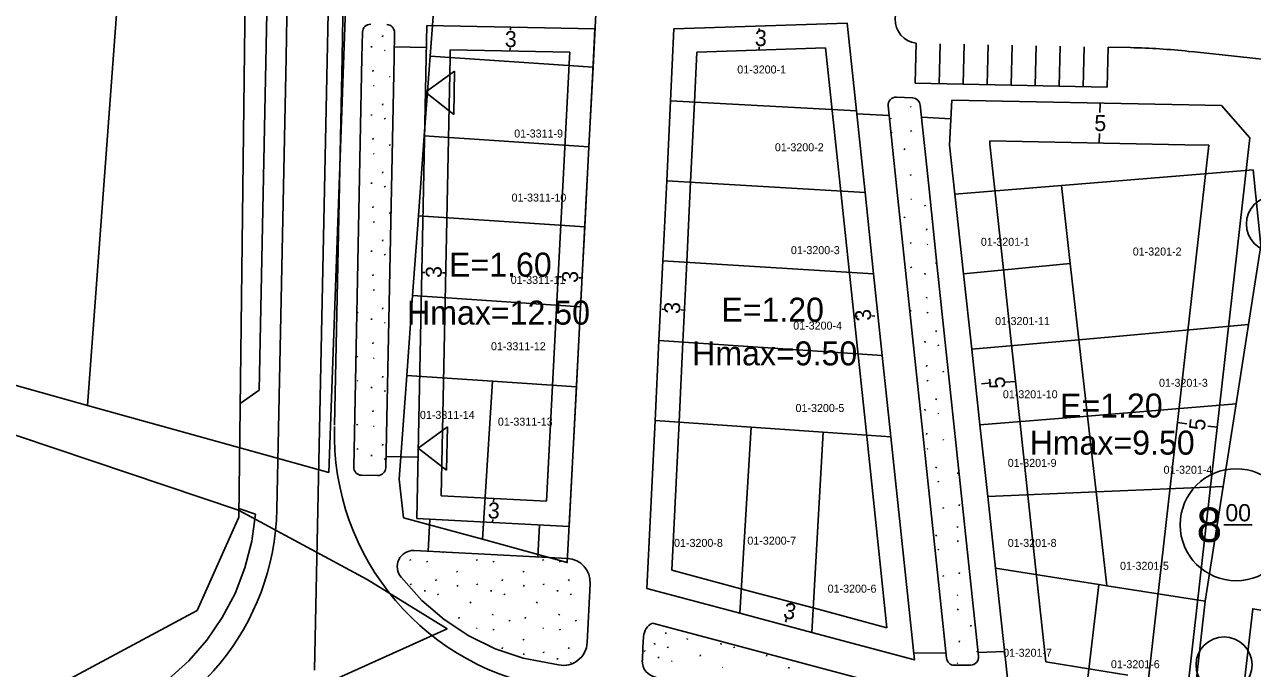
# Model space of a CAD drawing. Extents: x 419396 to 421519, y 4453567 to 4456767.
# Drawn here: x 420396.5 to 420549.9, y 4454436.5 to 4454516.9 of the extents above; entities that cross this region are included whole.
import ezdxf

# ---------------------------------------------------------------- set-up
doc = ezdxf.new("R2010")
doc.units = 0
for name, color, linetype in [('0_KADASTRO', 7, 'Continuous'), ('Level 16', 7, 'Continuous'), ('Level 20', 7, 'Continuous'), ('Level 28', 7, 'Continuous'), ('Level 29', 7, 'Continuous'), ('Level 30', 7, 'Continuous'), ('Level 41', 7, 'Continuous'), ('Level 55', 7, 'Continuous'), ('Level 58', 7, 'Continuous'), ('Level 62', 7, 'Continuous'), ('Level 9', 7, 'Continuous')]:
    doc.layers.add(name, color=color, linetype=linetype)

msp = doc.modelspace()

# ---------------------------------------------------------------- linework, layer by layer
at = {"layer": '0_KADASTRO'}
for points in [[(420388.29, 4454473.82), (420396.15, 4454590.13), (420397.27, 4454605.49), (420411.29, 4454607.72), (420413.06, 4454586.21), (420404.4, 4454469.34)], [(420404.4, 4454469.34), (420413.06, 4454586.21), (420428.47, 4454594.05), (420435.75, 4454599.28), (420439.04, 4454586.15), (420434.51, 4454460.97)], [(420447.18, 4454512.99), (420447.92, 4454522.96), (420468.06, 4454521.61), (420467.54, 4454511.62)], [(420477.22, 4454507.39), (420477.65, 4454516.39), (420499.29, 4454517.1), (420500.44, 4454506.16)], [(420446.46, 4454503.01), (420447.18, 4454512.99), (420467.54, 4454511.62), (420467.02, 4454501.64)], [(420476.74, 4454497.41), (420477.22, 4454507.39), (420500.44, 4454506.16), (420501.52, 4454495.96)], [(420445.72, 4454493.04), (420446.46, 4454503.01), (420467.02, 4454501.64), (420466.5, 4454491.64)], [(420320.37, 4454499), (420353.67, 4454483.99), (420381.85, 4454470.14), (420423.24, 4454456.24), (420439.33, 4454447.56), (420449.3, 4454441.41), (420436.11, 4454435.44), (420420.26, 4454427.93), (420390.68, 4454416.1), (420329.86, 4454402.38), (420323.67, 4454464.08)], [(420526.05, 4454496.81), (420550, 4454498.77), (420550.96, 4454489.32), (420549.42, 4454479.43), (420528.24, 4454477.55), (420527.16, 4454487.06)], [(420476.25, 4454487.42), (420476.74, 4454497.41), (420501.52, 4454495.96), (420502.59, 4454485.77)], [(420512.75, 4454495.73), (420526.05, 4454496.81), (420527.16, 4454487.06), (420513.83, 4454485.79)], [(420445, 4454483.07), (420445.72, 4454493.04), (420466.5, 4454491.64), (420465.98, 4454481.66)], [(420475.77, 4454477.43), (420476.25, 4454487.42), (420502.59, 4454485.77), (420503.67, 4454475.58)], [(420513.83, 4454485.79), (420527.16, 4454487.06), (420528.24, 4454477.55), (420514.85, 4454476.35)], [(420444.26, 4454473.08), (420445, 4454483.07), (420465.98, 4454481.66), (420465.46, 4454471.67), (420454.98, 4454472.37)], [(420528.24, 4454477.55), (420549.42, 4454479.43), (420547.87, 4454469.55), (420529.33, 4454468.01)], [(420475.29, 4454467.43), (420475.77, 4454477.43), (420503.67, 4454475.58), (420504.75, 4454465.39), (420496.28, 4454465.98), (420487.29, 4454466.6)], [(420514.85, 4454476.35), (420528.24, 4454477.55), (420529.33, 4454468.01), (420515.87, 4454466.9)], [(420443.31, 4454460.12), (420444.26, 4454473.08), (420454.98, 4454472.37), (420453.71, 4454452.6), (420443.86, 4454455.3)], [(420453.71, 4454452.6), (420454.98, 4454472.37), (420465.46, 4454471.67), (420464.32, 4454449.7)], [(420529.33, 4454468.01), (420547.87, 4454469.55), (420546.26, 4454459.18), (420530.4, 4454458.52)], [(420474.27, 4454446.46), (420475.29, 4454467.43), (420487.29, 4454466.6), (420485.86, 4454443.37)], [(420515.87, 4454466.9), (420529.33, 4454468.01), (420530.4, 4454458.52), (420516.85, 4454457.96)], [(420485.86, 4454443.37), (420487.29, 4454466.6), (420496.28, 4454465.98), (420494.89, 4454440.95)], [(420494.89, 4454440.95), (420496.28, 4454465.98), (420504.75, 4454465.39), (420507.69, 4454437.53)], [(420516.85, 4454457.96), (420530.4, 4454458.52), (420531.74, 4454446.8), (420530.73, 4454446.96), (420521.76, 4454448.38), (420517.81, 4454449.01)], [(420530.4, 4454458.52), (420546.26, 4454459.18), (420544.03, 4454444.85), (420531.74, 4454446.8)], [(420517.81, 4454449.01), (420521.76, 4454448.38), (420530.73, 4454446.96), (420528.91, 4454431.42), (420520.67, 4454432.78), (420519.55, 4454432.97)], [(420528.91, 4454431.42), (420530.73, 4454446.96), (420531.74, 4454446.8), (420544.03, 4454444.85), (420542.26, 4454429.23), (420533.58, 4454430.66)], [(420547.89, 4454425.95), (420548.01, 4454426.99), (420549.96, 4454443.91), (420562.54, 4454441.84), (420560.5, 4454423.87)]]:
    msp.add_lwpolyline(points, close=True, dxfattribs=at)
at = {"layer": 'Level 16'}
for p, q in [((420450.25, 4454511.11), (420446.59, 4454508.49)), ((420450.14, 4454505.71), (420450.25, 4454511.11)), ((420446.59, 4454508.49), (420450.14, 4454505.71)), ((420449.35, 4454466.64), (420445.7, 4454464.01)), ((420449.24, 4454461.24), (420449.35, 4454466.64)), ((420445.7, 4454464.01), (420449.24, 4454461.24))]:
    msp.add_line(p, q, dxfattribs=at)
at = {"layer": 'Level 20'}
for p, q in [((420457.22, 4454516.62), (420457.21, 4454516.22)), ((420488.31, 4454516.44), (420488.3, 4454516.04)), ((420449.7, 4454513.77), (420449.68, 4454512.81)), ((420449.7, 4454513.77), (420464.62, 4454513.47)), ((420457.16, 4454513.62), (420457.17, 4454514.02)), ((420464.59, 4454512.81), (420464.62, 4454513.47)), ((420480.52, 4454513.49), (420496.59, 4454514.01)), ((420488.3, 4454513.75), (420488.31, 4454514.15)), ((420449.68, 4454512.81), (420448.57, 4454458.03)), ((420461.71, 4454457.35), (420464.59, 4454512.81)), ((420530.89, 4454507.13), (420530.87, 4454505.93)), ((420517.1, 4454501.99), (420517.12, 4454502.41)), ((420541.46, 4454501.92), (420517.12, 4454502.41)), ((420530.79, 4454502.13), (420530.81, 4454503.33)), ((420544.46, 4454501.85), (420536.64, 4454432.5)), ((420541.46, 4454501.92), (420541.46, 4454501.92)), ((420544.46, 4454501.85), (420541.46, 4454501.92)), ((420446.14, 4454485.96), (420446.54, 4454485.95)), ((420449.14, 4454485.9), (420448.74, 4454485.91)), ((420463.17, 4454485.41), (420463.57, 4454485.39)), ((420466.16, 4454485.26), (420465.76, 4454485.28)), ((420476.16, 4454481.36), (420476.56, 4454481.33)), ((420478.9, 4454481.24), (420478.5, 4454481.26)), ((420500.16, 4454480.45), (420500.56, 4454480.45)), ((420502.75, 4454480.5), (420502.35, 4454480.51)), ((420516.07, 4454472.05), (420517.26, 4454472.15)), ((420520.29, 4454472.33), (420519.09, 4454472.25)), ((420540.55, 4454467.18), (420541.74, 4454467.04)), ((420545.52, 4454466.62), (420544.33, 4454466.75)), ((420448.57, 4454458.03), (420461.71, 4454457.35)), ((420455.14, 4454457.69), (420455.12, 4454457.29)), ((420454.99, 4454454.69), (420455.01, 4454455.09)), ((420492.25, 4454444.76), (420492.16, 4454444.37)), ((420491.59, 4454442.26), (420491.7, 4454442.64))]:
    msp.add_line(p, q, dxfattribs=at)
for points in [[(420477.38, 4454448.74), (420478.28, 4454467.29), (420478.77, 4454477.29), (420479.25, 4454487.27), (420479.73, 4454497.26), (420480.21, 4454507.25), (420480.52, 4454513.49)], [(420496.59, 4454514.01), (420497.46, 4454505.84), (420498.54, 4454495.65), (420499.61, 4454485.46), (420500.69, 4454475.26), (420501.77, 4454465.07), (420504.25, 4454441.55)], [(420524.11, 4454437.28), (420522.78, 4454449.54), (420521.82, 4454458.49), (420520.84, 4454467.44), (420519.82, 4454476.89), (420518.8, 4454486.33), (420517.1, 4454501.99)], [(420504.25, 4454441.55), (420495.67, 4454443.85), (420486.64, 4454446.26), (420477.38, 4454448.74)], [(420534.35, 4454435.6), (420529.72, 4454436.36), (420524.11, 4454437.28)]]:
    msp.add_lwpolyline(points, dxfattribs=at)
at = {"layer": 'Level 28'}
for p, q in [((420438.74, 4454516), (420438.67, 4454512.81)), ((420438.74, 4454516), (420438.67, 4454512.81)), ((420442.74, 4454515.92), (420442.68, 4454512.81)), ((420442.74, 4454515.92), (420442.68, 4454512.81)), ((420442.7, 4454514.16), (420446.7, 4454514.08)), ((420438.67, 4454512.81), (420437.64, 4454461.63)), ((420438.67, 4454512.81), (420437.64, 4454461.63)), ((420442.68, 4454512.81), (420441.64, 4454461.55)), ((420442.68, 4454512.81), (420441.64, 4454461.55)), ((420507.47, 4454507.76), (420505.44, 4454507.86)), ((420504.52, 4454505.57), (420500.48, 4454505.78)), ((420546.04, 4454506.82), (420549.6, 4454502.77)), ((420512.25, 4454505.17), (420508.57, 4454505.37)), ((420425.83, 4454471.25), (420423.46, 4454469.58)), ((420441.67, 4454462.96), (420445.67, 4454462.88)), ((420438.62, 4454460.61), (420440.62, 4454460.57)), ((420438.62, 4454460.61), (420440.62, 4454460.57)), ((420423.3, 4454456.43), (420425.36, 4454455.74)), ((420464.55, 4454454.19), (420445.51, 4454455.18)), ((420447.16, 4454455.09), (420446.95, 4454451.1)), ((420460.86, 4454454.38), (420460.66, 4454450.39)), ((420445.18, 4454451.19), (420464.34, 4454450.2)), ((420443.58, 4454447.86), (420446.17, 4454444.96)), ((420467.18, 4454447.05), (420466.8, 4454439.69)), ((420446.17, 4454444.96), (420448.95, 4454442.56)), ((420448.95, 4454442.56), (420452.02, 4454440.54)), ((420452.02, 4454440.54), (420455.32, 4454438.93)), ((420473.78, 4454439.09), (420473.85, 4454440.44)), ((420455.32, 4454438.93), (420458.8, 4454437.76)), ((420473.7, 4454437.46), (420473.78, 4454439.09)), ((420511.62, 4454438.4), (420507.6, 4454438.38)), ((420518.94, 4454438.57), (420515.64, 4454438.44)), ((420458.8, 4454437.76), (420463.23, 4454436.9)), ((420512.7, 4454436.85), (420514.71, 4454436.88))]:
    msp.add_line(p, q, dxfattribs=at)
for points in [[(420504.4, 4454506.76), (420505.5, 4454496.38), (420506.57, 4454486.19), (420507.65, 4454476), (420508.73, 4454465.81), (420511.69, 4454437.74)], [(420508.41, 4454506.86), (420509.48, 4454496.8), (420510.55, 4454486.61), (420511.63, 4454476.42), (420512.71, 4454466.23), (420515.69, 4454437.99)], [(420502.46, 4454434.79), (420493.86, 4454437.09), (420484.83, 4454439.5), (420474.97, 4454442.13)]]:
    msp.add_lwpolyline(points, dxfattribs=at)
for centre, radius, start, end in [((420439.74, 4454515.98), 1, 88.8411, 178.8411), ((420439.74, 4454515.98), 1, 88.8411, 178.8411), ((420441.74, 4454515.94), 1, 358.8411, 88.8411), ((420441.74, 4454515.94), 1, 358.8411, 88.8411), ((420505.39, 4454506.86), 1, 87.0144, 186.0491), ((420507.41, 4454506.76), 1, 6.0413, 87.0184), ((420438.64, 4454461.61), 1, 178.8411, 268.8411), ((420438.64, 4454461.61), 1, 178.8411, 268.8411), ((420440.64, 4454461.57), 1, 268.8411, 358.8411), ((420440.64, 4454461.57), 1, 268.8411, 358.8411), ((420445.07, 4454449.19), 2, 87.0363, 221.7532), ((420464.19, 4454447.2), 3, 357.0363, 87.0363), ((420475.85, 4454440.34), 2, 116.0278, 177.0363), ((420463.81, 4454439.84), 3, 258.9123, 357.0363), ((420514.69, 4454437.88), 1, 271.0633, 6.0242), ((420475.69, 4454437.36), 2, 177.0363, 262.6282), ((420512.69, 4454437.85), 1, 186.0244, 271.0368)]:
    msp.add_arc(centre, radius, start, end, dxfattribs=at)
at = {"layer": 'Level 29'}
for p, q in [((420427.92, 4454574.73), (420425.83, 4454471.25)), ((420446.68, 4454512.81), (420446.76, 4454516.83)), ((420446.76, 4454516.83), (420467.78, 4454516.41)), ((420467.78, 4454516.41), (420467.59, 4454512.81)), ((420477.65, 4454516.39), (420499.29, 4454517.1)), ((420445.51, 4454455.18), (420446.68, 4454512.81)), ((420467.59, 4454512.81), (420464.55, 4454454.2)), ((420512.08, 4454501.85), (420512.37, 4454507.5)), ((420512.37, 4454507.5), (420541.99, 4454506.91)), ((420541.99, 4454506.91), (420546.04, 4454506.82)), ((420549.6, 4454502.77), (420541.04, 4454426.89))]:
    msp.add_line(p, q, dxfattribs=at)
for points in [[(420474.27, 4454446.46), (420475.29, 4454467.43), (420475.77, 4454477.43), (420476.25, 4454487.42), (420476.74, 4454497.41), (420477.22, 4454507.39), (420477.65, 4454516.39)], [(420499.29, 4454517.1), (420500.44, 4454506.16), (420501.52, 4454495.96), (420502.59, 4454485.77), (420503.67, 4454475.58), (420504.75, 4454465.39), (420507.69, 4454437.53)], [(420519.55, 4454432.97), (420517.81, 4454449.01), (420516.85, 4454457.96), (420515.87, 4454466.9), (420514.85, 4454476.35), (420513.83, 4454485.79), (420512.08, 4454501.85)], [(420425.36, 4454455.74), (420424.89, 4454452.35), (420424.04, 4454449.04), (420422.81, 4454445.84), (420421.22, 4454442.82), (420419.28, 4454440), (420417.04, 4454437.42), (420414.51, 4454435.11), (420411.73, 4454433.12), (420408.74, 4454431.46), (420405.58, 4454430.16), (420402.29, 4454429.23)], [(420507.69, 4454437.53), (420494.89, 4454440.95), (420485.86, 4454443.37), (420474.27, 4454446.46)]]:
    msp.add_lwpolyline(points, dxfattribs=at)
at = {"layer": 'Level 41'}
for p, q in [((420441.22, 4454515.39), (420441.29, 4454515.55)), ((420439.85, 4454514.22), (420439.87, 4454514.06)), ((420441.48, 4454513.75), (420441.55, 4454513.64)), ((420440.02, 4454511.07), (420440.09, 4454511.23)), ((420442.11, 4454510.46), (420442.18, 4454510.35)), ((420440.13, 4454509.34), (420440.2, 4454509.23)), ((420441.22, 4454506.88), (420441.29, 4454507.04)), ((420439.85, 4454505.71), (420439.87, 4454505.55)), ((420507.19, 4454506.71), (420507.26, 4454506.6)), ((420441.48, 4454505.24), (420441.55, 4454505.13)), ((420504.73, 4454505.25), (420504.8, 4454505.15)), ((420440.02, 4454502.56), (420440.09, 4454502.72)), ((420504.79, 4454503.33), (420504.86, 4454503.49)), ((420507.26, 4454503.68), (420507.33, 4454503.57)), ((420442.11, 4454501.95), (420442.18, 4454501.84)), ((420506.41, 4454501.27), (420506.48, 4454501.43)), ((420440.13, 4454500.83), (420440.2, 4454500.72)), ((420441.22, 4454498.37), (420441.29, 4454498.53)), ((420507.19, 4454498.2), (420507.26, 4454498.09)), ((420509.29, 4454498), (420509.36, 4454497.9)), ((420439.85, 4454497.2), (420439.87, 4454497.04)), ((420441.48, 4454496.73), (420441.55, 4454496.62)), ((420507.26, 4454495.17), (420507.33, 4454495.06)), ((420440.02, 4454494.05), (420440.09, 4454494.21)), ((420442.11, 4454493.44), (420442.18, 4454493.33)), ((420509.01, 4454494.38), (420509.03, 4454494.22)), ((420440.13, 4454492.32), (420440.2, 4454492.21)), ((420506.41, 4454492.76), (420506.48, 4454492.92)), ((420509.18, 4454491.23), (420509.25, 4454491.39)), ((420439.85, 4454488.69), (420439.87, 4454488.53)), ((420441.22, 4454489.86), (420441.29, 4454490.02)), ((420507.19, 4454489.69), (420507.26, 4454489.58)), ((420509.29, 4454489.5), (420509.36, 4454489.39)), ((420441.48, 4454488.22), (420441.55, 4454488.11)), ((420510.38, 4454487.04), (420510.46, 4454487.2)), ((420440.02, 4454485.54), (420440.09, 4454485.7)), ((420507.26, 4454486.66), (420507.33, 4454486.55)), ((420509.01, 4454485.87), (420509.03, 4454485.71)), ((420442.11, 4454484.93), (420442.12, 4454484.92)), ((420510.64, 4454485.4), (420510.68, 4454485.34)), ((420438.1, 4454483.9), (420438.1, 4454483.89)), ((420440.13, 4454483.81), (420440.2, 4454483.7)), ((420509.18, 4454482.72), (420509.25, 4454482.88)), ((420438.09, 4454480.97), (420438.17, 4454480.86)), ((420441.22, 4454481.35), (420441.29, 4454481.51)), ((420507.19, 4454481.18), (420507.26, 4454481.07)), ((420509.29, 4454480.99), (420509.36, 4454480.88)), ((420439.85, 4454480.18), (420439.87, 4454480.02)), ((420441.48, 4454479.71), (420441.55, 4454479.6)), ((420510.38, 4454478.53), (420510.46, 4454478.69)), ((420440.02, 4454477.03), (420440.09, 4454477.19)), ((420509.01, 4454477.36), (420509.03, 4454477.2)), ((420510.64, 4454476.89), (420510.71, 4454476.78)), ((420438.03, 4454475.49), (420438.1, 4454475.38)), ((420440.13, 4454475.3), (420440.2, 4454475.19)), ((420509.18, 4454474.21), (420509.25, 4454474.37)), ((420511.27, 4454473.6), (420511.34, 4454473.49)), ((420438.09, 4454472.46), (420438.17, 4454472.35)), ((420441.22, 4454472.84), (420441.29, 4454473)), ((420509.29, 4454472.47), (420509.36, 4454472.37)), ((420439.85, 4454471.67), (420439.87, 4454471.51)), ((420441.48, 4454471.2), (420441.55, 4454471.09)), ((420510.38, 4454470.02), (420510.46, 4454470.18)), ((420440.02, 4454468.52), (420440.09, 4454468.68)), ((420509.01, 4454468.85), (420509.03, 4454468.69)), ((420510.64, 4454468.38), (420510.71, 4454468.27)), ((420438.03, 4454466.98), (420438.1, 4454466.87)), ((420440.13, 4454466.79), (420440.2, 4454466.68)), ((420509.18, 4454465.7), (420509.25, 4454465.86)), ((420441.22, 4454464.33), (420441.29, 4454464.49)), ((420511.27, 4454465.09), (420511.34, 4454464.98)), ((420438.09, 4454463.95), (420438.17, 4454463.84)), ((420439.85, 4454463.16), (420439.87, 4454463)), ((420441.48, 4454462.69), (420441.55, 4454462.58)), ((420509.29, 4454463.96), (420509.36, 4454463.86)), ((420513.03, 4454462.7), (420513.09, 4454462.61)), ((420510.38, 4454461.51), (420510.46, 4454461.67)), ((420510.64, 4454459.87), (420510.71, 4454459.76)), ((420513.08, 4454460.78), (420513.16, 4454460.94)), ((420511.27, 4454456.58), (420511.34, 4454456.47)), ((420513.26, 4454456.78), (420513.33, 4454456.94)), ((420513.03, 4454454.19), (420513.1, 4454454.09)), ((420510.38, 4454453), (420510.46, 4454453.16)), ((420513.08, 4454452.27), (420513.16, 4454452.43)), ((420448.77, 4454450.99), (420448.84, 4454450.89)), ((420510.64, 4454451.36), (420510.71, 4454451.25)), ((420444.68, 4454450.06), (420444.75, 4454449.96)), ((420446.78, 4454449.87), (420446.85, 4454449.76)), ((420452.98, 4454450.06), (420453.05, 4454449.96)), ((420455.07, 4454449.87), (420455.15, 4454449.76)), ((420461.27, 4454450.06), (420461.34, 4454449.96)), ((420463.37, 4454449.87), (420463.44, 4454449.76)), ((420447.88, 4454447.42), (420447.95, 4454447.58)), ((420450.52, 4454448.61), (420450.59, 4454448.5)), ((420456.17, 4454447.42), (420456.24, 4454447.58)), ((420458.81, 4454448.61), (420458.88, 4454448.5)), ((420464.46, 4454447.42), (420464.54, 4454447.58)), ((420511.27, 4454448.07), (420511.34, 4454447.96)), ((420513.26, 4454448.27), (420513.33, 4454448.43)), ((420444.75, 4454447.03), (420444.82, 4454446.93)), ((420446.51, 4454446.24), (420446.53, 4454446.08)), ((420448.14, 4454445.77), (420448.21, 4454445.67)), ((420450.58, 4454446.69), (420450.65, 4454446.85)), ((420453.04, 4454447.03), (420453.11, 4454446.93)), ((420454.8, 4454446.24), (420454.82, 4454446.08)), ((420456.43, 4454445.77), (420456.5, 4454445.67)), ((420458.87, 4454446.69), (420458.94, 4454446.85)), ((420461.34, 4454447.03), (420461.41, 4454446.93)), ((420463.09, 4454446.24), (420463.11, 4454446.08)), ((420464.72, 4454445.77), (420464.79, 4454445.67)), ((420467.16, 4454446.69), (420467.17, 4454446.71)), ((420513.03, 4454445.68), (420513.1, 4454445.58)), ((420452.19, 4454444.63), (420452.27, 4454444.79)), ((420460.49, 4454444.63), (420460.56, 4454444.79)), ((420450.76, 4454442.69), (420450.83, 4454442.85)), ((420454.97, 4454443.1), (420455.04, 4454443.26)), ((420459.05, 4454442.69), (420459.12, 4454442.85)), ((420463.26, 4454443.1), (420463.33, 4454443.26)), ((420513.08, 4454443.76), (420513.16, 4454443.92)), ((420452.98, 4454441.55), (420453.05, 4454441.45)), ((420455.07, 4454441.36), (420455.15, 4454441.25)), ((420457.06, 4454442.48), (420457.13, 4454442.38)), ((420461.27, 4454441.55), (420461.34, 4454441.45)), ((420463.37, 4454441.36), (420463.44, 4454441.25)), ((420465.35, 4454442.48), (420465.42, 4454442.38)), ((420514.7, 4454441.7), (420514.77, 4454441.86)), ((420458.81, 4454440.1), (420458.88, 4454439.99)), ((420475.22, 4454439.62), (420475.24, 4454439.46)), ((420476.59, 4454440.79), (420476.66, 4454440.95)), ((420479.29, 4454440.07), (420479.36, 4454440.22)), ((420481.83, 4454440.3), (420481.83, 4454440.3)), ((420483.51, 4454439.62), (420483.53, 4454439.46)), ((420513.26, 4454439.76), (420513.33, 4454439.92)), ((420456.17, 4454438.91), (420456.24, 4454439.07)), ((420458.87, 4454438.18), (420458.94, 4454438.34)), ((420461.34, 4454438.52), (420461.41, 4454438.42)), ((420464.46, 4454438.91), (420464.54, 4454439.07)), ((420473.95, 4454438.69), (420474.02, 4454438.58)), ((420476.85, 4454439.15), (420476.92, 4454439.04)), ((420480.91, 4454438), (420480.98, 4454438.17)), ((420485.14, 4454439.15), (420485.21, 4454439.04)), ((420489.2, 4454438), (420489.27, 4454438.17)), ((420515.48, 4454438.63), (420515.55, 4454438.52)), ((420463.09, 4454437.73), (420463.11, 4454437.57)), ((420464.72, 4454437.26), (420464.79, 4454437.16)), ((420475.71, 4454437.89), (420475.73, 4454437.73)), ((420477.34, 4454437.42), (420477.41, 4454437.32)), ((420483.73, 4454436.58), (420483.75, 4454436.63)), ((420491.97, 4454436.47), (420492.04, 4454436.63)), ((420513.03, 4454437.17), (420513.1, 4454437.07))]:
    msp.add_line(p, q, dxfattribs=at)
at = {"layer": 'Level 55'}
for centre in [(420552.66, 4454492.01), (420546.37, 4454436.9)]:
    msp.add_circle(centre, 3.5, dxfattribs=at)
at = {"layer": 'Level 58'}
msp.add_line((420546.33, 4454454.42), (420549.88, 4454454.42), dxfattribs=at)
msp.add_circle((420547.89, 4454454.42), 7, dxfattribs=at)
at = {"layer": 'Level 62'}
for p, q in [((420429.18, 4454512.81), (420430.68, 4454587.2)), ((420429.18, 4454512.81), (420430.68, 4454587.2)), ((420436.34, 4454520.66), (420436.18, 4454512.81)), ((420507.9, 4454514.6), (420507.79, 4454509.6)), ((420510.9, 4454514.54), (420510.79, 4454509.54)), ((420513.89, 4454514.48), (420513.79, 4454509.48)), ((420516.89, 4454514.42), (420516.79, 4454509.42)), ((420519.89, 4454514.36), (420519.79, 4454509.36)), ((420522.89, 4454514.29), (420522.79, 4454509.3)), ((420525.89, 4454514.24), (420525.79, 4454509.24)), ((420528.89, 4454514.17), (420528.79, 4454509.17)), ((420531.89, 4454514.11), (420531.79, 4454509.11)), ((420534.68, 4454514.06), (420531.89, 4454514.11)), ((420542.7, 4454513.51), (420541.95, 4454513.59)), ((420638.84, 4454503.13), (420542.7, 4454513.51)), ((420428.04, 4454456.32), (420429.18, 4454512.81)), ((420436.18, 4454512.81), (420435.25, 4454466.88)), ((420531.79, 4454509.11), (420507.79, 4454509.6))]:
    msp.add_line(p, q, dxfattribs=at)
for centre, radius, start, end in [((420508.3, 4454517.59), 3.02, 95.3668, 262.3154), ((420533, 4454430.65), 83.42, 83.8377, 88.8411), ((420467.25, 4454465.7), 32.02, 178.1967, 262.6282), ((420396.79, 4454456.95), 31.25, 282.4285, 358.8411)]:
    msp.add_arc(centre, radius, start, end, dxfattribs=at)
at = {"layer": 'Level 9'}
for p, q in [((420432.76, 4454436.23), (420438.68, 4454721.11)), ((420426.53, 4454716.81), (420423.29, 4454455.37)), ((420423.29, 4454455.37), (420418.1, 4454443.69)), ((420418.1, 4454443.69), (420399.93, 4454433.96))]:
    msp.add_line(p, q, dxfattribs=at)

# ---------------------------------------------------------------- texts
at = {"layer": '0_KADASTRO'}
for s, p in [('01-3200-1', (420485.56, 4454510.82)), ('01-3311-9', (420457.69, 4454502.82)), ('01-3200-2', (420490.26, 4454501.1)), ('01-3311-10', (420457.36, 4454494.81)), ('01-3201-1', (420515.99, 4454489.28)), ('01-3200-3', (420492.26, 4454488.24)), ('01-3201-2', (420534.97, 4454488.07)), ('01-3311-11', (420457.25, 4454484.52)), ('01-3200-4', (420492.55, 4454478.81)), ('01-3201-11', (420517.77, 4454479.38)), ('01-3311-12', (420454.79, 4454476.23)), ('01-3201-3', (420538.25, 4454471.66)), ('01-3201-10', (420518.74, 4454470.23)), ('01-3311-14', (420445.91, 4454467.65)), ('01-3200-5', (420492.84, 4454468.51)), ('01-3311-13', (420455.65, 4454466.8)), ('01-3201-9', (420519.35, 4454461.65)), ('01-3201-4', (420538.82, 4454460.79)), ('01-3200-8', (420477.66, 4454451.65)), ('01-3200-7', (420486.82, 4454451.93)), ('01-3201-8', (420519.35, 4454451.65)), ('01-3201-5', (420533.38, 4454448.79)), ('01-3200-6', (420496.85, 4454445.93)), ('01-3201-7', (420518.78, 4454437.92)), ('01-3201-6', (420532.24, 4454436.49))]:
    msp.add_text(s, height=1, dxfattribs=at).set_placement(p)
at = {"layer": 'Level 20'}
for s, rotation, p in [('3', 358.8411, (420487.74, 4454514.27)), ('3', 358.8411, (420456.5, 4454514.14)), ('5', 358.8411, (420530.15, 4454503.64)), ('3', 88.8411, (420448.62, 4454485.25)), ('3', 87.0363, (420465.63, 4454484.62)), ('3', 87.0363, (420478.39, 4454480.73)), ('3', 95.6052, (420502.34, 4454479.97)), ('5', 94.5663, (420519.07, 4454471.52)), ('5', 83.5653, (420543.95, 4454466.12)), ('3', 357.0363, (420454.35, 4454455.23)), ('3', 348.9617, (420491.21, 4454442.79))]:
    msp.add_text(s, height=2, rotation=rotation, dxfattribs=at).set_placement(p)
at = {"layer": 'Level 30'}
for s, p in [('E=1.60', (420449.55, 4454485.43)), ('Hmax=12.50', (420444.3, 4454479.43)), ('E=1.20', (420483.56, 4454479.8)), ('Hmax=9.50', (420479.92, 4454474.34)), ('E=1.20', (420525.88, 4454467.82)), ('Hmax=9.50', (420522.08, 4454463.18))]:
    msp.add_text(s, height=3, dxfattribs=at).set_placement(p)
at = {"layer": 'Level 58'}
for s, height, p in [('8', 4.3, (420542.94, 4454452.27)), ('00', 2.152, (420546.54, 4454454.85))]:
    msp.add_text(s, height=height, dxfattribs=at).set_placement(p)

doc.saveas('drawing.dxf')
